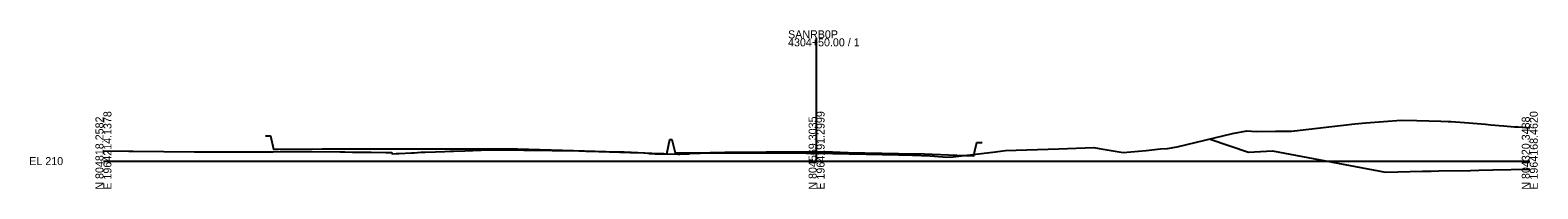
# Model space of a CAD drawing. Extents: x 1995641 to 1997170, y 790368 to 809963.
# Drawn here: x 1996641 to 1997170, y 795368 to 795424 of the extents above; entities that cross this region are included whole.
import ezdxf

# ---------------------------------------------------------------- set-up
doc = ezdxf.new("R2010")
doc.units = 0
for name, color, linetype in [('Default', 7, 'Continuous'), ('RD_GPK_XS_Cell', 7, 'Continuous'), ('RD_Sketch1', 7, 'Continuous'), ('RD_XS_ExGround', 7, 'Continuous'), ('RD_XS_Pave', 7, 'Continuous')]:
    doc.layers.add(name, color=color, linetype=linetype)

msp = doc.modelspace()

# ---------------------------------------------------------------- linework, layer by layer
at = {"layer": 'RD_GPK_XS_Cell'}
for p, q in [((1996917.06, 795378.11), (1996917.06, 795421.08)), ((1996667.06, 795378.11), (1996917.06, 795378.11)), ((1996917.06, 795378.11), (1997167.06, 795378.11))]:
    msp.add_line(p, q, dxfattribs=at)
at = {"layer": 'RD_Sketch1'}
msp.add_line((1997076.88, 795381.71), (1997116.53, 795374.22), dxfattribs=at)
at = {"layer": 'RD_XS_ExGround'}
msp.add_lwpolyline([(1996667.06, 795381.66), (1996675.99, 795381.59), (1996677.51, 795381.57), (1996698.99, 795381.41), (1996700.43, 795381.38), (1996702.28, 795381.36), (1996725.07, 795381.4), (1996726.56, 795381.41), (1996728.97, 795381.46), (1996740.26, 795381.47), (1996750.05, 795381.34), (1996751.68, 795381.33), (1996754.37, 795381.29), (1996760.87, 795381.19), (1996766.08, 795381.09), (1996768.07, 795381.07), (1996768.32, 795380.62), (1996769.72, 795380.72), (1996770.67, 795380.81), (1996775.07, 795381.03), (1996775.97, 795381.05), (1996778.32, 795381.19), (1996779.89, 795381.24), (1996783.46, 795381.4), (1996786.69, 795381.51), (1996788.58, 795381.58), (1996789.81, 795381.6), (1996793.73, 795381.74), (1996799.49, 795381.92), (1996803.57, 795382.02), (1996814.41, 795381.99), (1996820.31, 795381.97), (1996824.34, 795381.87), (1996833.73, 795381.65), (1996836.15, 795381.59), (1996837.15, 795381.57), (1996851.74, 795381.16), (1996852.71, 795381.14), (1996853.54, 795381.11), (1996856.44, 795380.97), (1996857.87, 795380.9), (1996858.43, 795380.79), (1996860.44, 795380.71), (1996861.8, 795380.65), (1996863.03, 795380.63), (1996868.38, 795380.56), (1996869.1, 795380.59), (1996871.27, 795380.62), (1996871.71, 795380.67), (1996872.28, 795380.69), (1996872.73, 795380.79), (1996874.88, 795380.86), (1996876.23, 795380.91), (1996884.45, 795380.99), (1996893.51, 795381.06), (1996894.98, 795381.04), (1996895.54, 795381.03), (1996898.74, 795380.99), (1996911.39, 795380.98), (1996913.38, 795380.93), (1996917.06, 795380.87), (1996928.5, 795380.69), (1996934.41, 795380.55), (1996945.74, 795380.31), (1996950.71, 795380.15), (1996956.83, 795379.9), (1996961.34, 795379.63), (1996963.83, 795379.51), (1996978.82, 795381.24), (1996983.23, 795381.79), (1997001.99, 795382.4), (1997014.27, 795382.84), (1997016.14, 795382.56), (1997024.5, 795381.08), (1997032.54, 795381.86), (1997037.63, 795382.38), (1997040.02, 795382.58), (1997043.4, 795383.09), (1997062.8, 795387.79), (1997067.87, 795388.7), (1997071.15, 795388.52), (1997077.94, 795388.64), (1997083.52, 795388.59), (1997084.63, 795388.74), (1997105.78, 795391.12), (1997108.33, 795391.43), (1997109.63, 795391.53), (1997121.93, 795392.44), (1997127.49, 795392.37), (1997135.83, 795392.08), (1997138.48, 795392.02), (1997139.53, 795391.94), (1997144.18, 795391.57), (1997151.5, 795390.99), (1997153.46, 795390.83), (1997157.88, 795390.46), (1997161.67, 795390.15), (1997162.98, 795390.07), (1997167.06, 795389.81)], dxfattribs=at)
at = {"layer": 'RD_XS_Pave'}
for points in [[(1996723.86, 795386.99), (1996725.64, 795386.96), (1996726.71, 795382.27), (1996728.43, 795382.29), (1996743.78, 795382.44), (1996765.27, 795382.43), (1996777.31, 795382.43), (1996781.7, 795382.41), (1996790.37, 795382.38), (1996804.86, 795382.38), (1996812.2, 795382.37), (1996828.02, 795381.93), (1996847.09, 795381.41), (1996849.55, 795381.3), (1996859.26, 795380.9), (1996863.46, 795380.74), (1996864.53, 795380.7), (1996865.62, 795385.65), (1996866.35, 795385.64), (1996867.44, 795380.96), (1996879.7, 795381.17), (1996884.88, 795381.26), (1996899.43, 795381.3), (1996917.06, 795381.36), (1996919.77, 795381.37), (1996922.59, 795381.3), (1996928.15, 795381.17), (1996945.75, 795380.8), (1996954.66, 795380.61), (1996954.73, 795380.61), (1996963.28, 795380.31), (1996972.17, 795380.01), (1996972.56, 795381.66), (1996973.26, 795384.67), (1996973.87, 795384.66), (1996975.08, 795384.66)], [(1997054.98, 795385.82), (1997068.5, 795381.27), (1997076.88, 795381.71)], [(1997116.53, 795374.22), (1997129.5, 795374.54), (1997131.45, 795374.59), (1997132.54, 795374.61), (1997135.18, 795374.65), (1997146.29, 795374.88), (1997149.2, 795374.95), (1997154.16, 795375.05), (1997166.91, 795375.32), (1997167.06, 795375.31)]]:
    msp.add_lwpolyline(points, dxfattribs=at)

# ---------------------------------------------------------------- texts
at = {"layer": 'Default'}
msp.add_text('-', height=0.0001, dxfattribs=at).set_placement((1996667.06, 795378.11))
msp.add_text('-', height=0.0001, dxfattribs=at).set_placement((1996667.06, 795378.11))
at = {"layer": 'RD_GPK_XS_Cell'}
for s, p in [('4304+50.00 / 1', (1996907.06, 795418.28)), ('SANRB0P', (1996907.06, 795421.08)), ('EL 210', (1996641.06, 795376.71))]:
    msp.add_text(s, height=2.8, dxfattribs=at).set_placement(p)
for s, p in [('E 1964214.1378', (1996669.86, 795368.11)), ('E 1964191.2999', (1996919.86, 795368.11)), ('E 1964168.4620', (1997169.86, 795368.11)), ('N 804818.2582', (1996667.06, 795368.11)), ('N 804569.3035', (1996917.06, 795368.11)), ('N 804320.3488', (1997167.06, 795368.11))]:
    msp.add_text(s, height=2.8, rotation=90, dxfattribs=at).set_placement(p)
at = {"layer": 'RD_Sketch1'}
for s, p in [('213.25', (1996916.85, 795381.26)), ('212.76', (1996916.85, 795380.77))]:
    msp.add_text(s, height=0.1, dxfattribs=at).set_placement(p)

doc.saveas('drawing.dxf')
